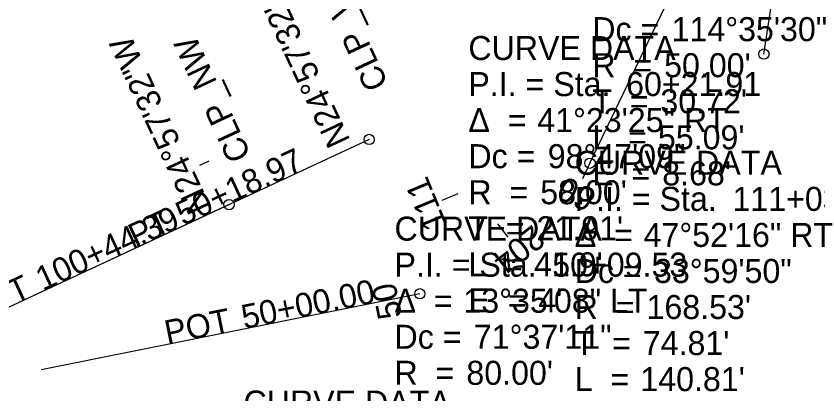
# Model space of a CAD drawing. Extents: x 1564517 to 1565226, y 635740 to 637455.
# Drawn here: x 1564729.9 to 1564823.3, y 636528.5 to 636572.5 of the extents above; entities that cross this region are included whole.
import ezdxf

# ---------------------------------------------------------------- set-up
doc = ezdxf.new("R2010")
doc.units = 0
for name, color, linetype in [('GK_Drainage_Nodes', 7, 'Continuous'), ('SC_Scratch10', 7, 'Continuous'), ('TX_P_1000', 7, 'Continuous'), ('UT_P_Water', 7, 'Continuous'), ('UT_P_Water_Cells', 7, 'Continuous'), ('UT_X_Sanitary_Pressure_Line', 7, 'Continuous'), ('UT_X_Water_Cells', 7, 'Continuous')]:
    doc.layers.add(name, color=color, linetype=linetype)

msp = doc.modelspace()

# ---------------------------------------------------------------- linework, layer by layer
at = {"layer": 'TX_P_1000'}
for p, q in [((1564796.769, 636555.382), (1564816.233, 636595.955)), ((1564771.061, 636558.156), (1564730.264, 636539.167)), ((1564776.961, 636540.174), (1564732.845, 636531.3))]:
    msp.add_line(p, q, dxfattribs=at)
at = {"layer": 'UT_P_Water_Cells'}
for p, q in [((1564817.022, 636568.096), (1564823.806, 636612.582)), ((1564796.769, 636555.382), (1564816.233, 636595.955)), ((1564771.061, 636558.156), (1564730.264, 636539.167)), ((1564796.769, 636555.382), (1564795.904, 636553.579)), ((1564781.384, 636551.813), (1564780.276, 636551.354)), ((1564754.742, 636550.56), (1564713.945, 636531.572)), ((1564785.988, 636548.34), (1564786.723, 636547.391)), ((1564776.961, 636540.174), (1564732.845, 636531.3)), ((1564776.961, 636540.174), (1564775.001, 636539.78))]:
    msp.add_line(p, q, dxfattribs=at)
for centre in [(1564817.022, 636568.096), (1564771.061, 636558.156), (1564796.769, 636555.382), (1564754.742, 636550.56), (1564776.961, 636540.174)]:
    msp.add_circle(centre, 0.6, dxfattribs=at)
at = {"layer": 'UT_X_Sanitary_Pressure_Line'}
for p, q in [((1564817.022, 636568.096), (1564823.806, 636612.582)), ((1564796.769, 636555.382), (1564816.233, 636595.955)), ((1564771.061, 636558.156), (1564730.264, 636539.167)), ((1564796.769, 636555.382), (1564795.904, 636553.579)), ((1564754.742, 636550.56), (1564713.945, 636531.572)), ((1564776.961, 636540.174), (1564732.845, 636531.3)), ((1564776.961, 636540.174), (1564775.001, 636539.78))]:
    msp.add_line(p, q, dxfattribs=at)
for centre in [(1564817.022, 636568.096), (1564771.061, 636558.156), (1564796.769, 636555.382), (1564754.742, 636550.56), (1564776.961, 636540.174)]:
    msp.add_circle(centre, 0.6, dxfattribs=at)
at = {"layer": 'UT_X_Water_Cells'}
for p, q in [((1564752.376, 636555.644), (1564751.288, 636555.137)), ((1564796.769, 636555.382), (1564795.904, 636553.579)), ((1564781.384, 636551.813), (1564779.536, 636551.049)), ((1564785.988, 636548.34), (1564787.213, 636546.759)), ((1564776.961, 636540.174), (1564775.001, 636539.78))]:
    msp.add_line(p, q, dxfattribs=at)
for centre in [(1564771.061, 636558.156), (1564796.769, 636555.382), (1564776.961, 636540.174)]:
    msp.add_circle(centre, 0.6, dxfattribs=at)

# ---------------------------------------------------------------- texts
at = {"layer": 'GK_Drainage_Nodes'}
for s, p in [('CLP_WL', (1564773.341, 636564.634)), ('N24°57\'32"W', (1564768.906, 636558.046)), ('N24°57\'32"W', (1564752.661, 636550.292)), ('CLP_NW', (1564757.357, 636556.318))]:
    msp.add_text(s, height=2.8, rotation=114.95884, dxfattribs=at).set_placement(p)
for s, p in [('Dc = ', (1564797.041, 636569.604)), ('114°35\'30"', (1564806.279, 636569.604)), ('CURVE DATA', (1564782.614, 636567.406)), ('R  = ', (1564797.041, 636565.404)), ("50.00'", (1564805.409, 636565.404)), ('P.I. = Sta. ', (1564782.614, 636563.206)), ('60+21.91', (1564800.983, 636563.206)), ('T  = ', (1564797.041, 636561.204)), ("30.72'", (1564804.973, 636561.204)), ('Δ  = ', (1564782.614, 636559.006)), ('41°23\'25" RT', (1564790.636, 636559.006)), ('L  = ', (1564797.041, 636557.004)), ("55.09'", (1564804.687, 636557.004)), ('Dc = ', (1564782.614, 636554.806)), ('98°47\'09"', (1564791.853, 636554.806)), ('CURVE DATA', (1564794.993, 636554.033)), ('E  = ', (1564797.041, 636552.804)), ("8.68'", (1564805.193, 636552.804)), ('R  = ', (1564782.614, 636550.606)), ("58.00'", (1564790.982, 636550.606)), ('P.I. = Sta. ', (1564794.993, 636549.833)), ('111+03.79', (1564813.362, 636549.833)), ('CURVE DATA', (1564774.011, 636546.365)), ('T  = ', (1564782.614, 636546.406)), ("21.91'", (1564790.547, 636546.406)), ('Δ  = ', (1564794.993, 636545.633)), ('47°52\'16" RT', (1564803.016, 636545.633)), ('P.I. = Sta. ', (1564774.011, 636542.165)), ('L  = ', (1564782.614, 636542.206)), ("41.9'", (1564790.261, 636542.206)), ('50+09.53', (1564792.38, 636542.165)), ('Dc = ', (1564794.993, 636541.433)), ('33°59\'50"', (1564804.232, 636541.433)), ('Δ  = ', (1564774.011, 636537.965)), ('13°35\'08" LT', (1564782.034, 636537.965)), ('E  = ', (1564782.614, 636538.006)), ("4'", (1564790.767, 636538.006)), ('R  = ', (1564794.993, 636537.233)), ("168.53'", (1564803.361, 636537.233)), ('Dc = ', (1564774.011, 636533.765)), ('71°37\'11"', (1564783.25, 636533.765)), ('T  = ', (1564794.993, 636533.033)), ("74.81'", (1564802.926, 636533.033)), ('R  = ', (1564774.011, 636529.565)), ("80.00'", (1564782.379, 636529.565)), ('L  = ', (1564794.993, 636528.833)), ("140.81'", (1564802.64, 636528.833)), ('CURVE DATA', (1564756.427, 636526.1))]:
    msp.add_text(s, height=2.8, dxfattribs=at).set_placement(p)
at = {"layer": 'SC_Scratch10'}
for s, p in [('CLP_WL', (1564773.341, 636564.634)), ('N24°57\'32"W', (1564768.906, 636558.046)), ('N24°57\'32"W', (1564752.661, 636550.292)), ('CLP_NW', (1564757.357, 636556.318))]:
    msp.add_text(s, height=2.8, rotation=114.95884, dxfattribs=at).set_placement(p)
for s, p in [('Dc = ', (1564797.041, 636569.604)), ('114°35\'30"', (1564806.279, 636569.604)), ('CURVE DATA', (1564782.614, 636567.406)), ('R  = ', (1564797.041, 636565.404)), ("50.00'", (1564805.409, 636565.404)), ('P.I. = Sta. ', (1564782.614, 636563.206)), ('60+21.91', (1564800.983, 636563.206)), ('T  = ', (1564797.041, 636561.204)), ("30.72'", (1564804.973, 636561.204)), ('Δ  = ', (1564782.614, 636559.006)), ('41°23\'25" RT', (1564790.636, 636559.006)), ('L  = ', (1564797.041, 636557.004)), ("55.09'", (1564804.687, 636557.004)), ('Dc = ', (1564782.614, 636554.806)), ('98°47\'09"', (1564791.853, 636554.806)), ('CURVE DATA', (1564794.993, 636554.033)), ('E  = ', (1564797.041, 636552.804)), ("8.68'", (1564805.193, 636552.804)), ('R  = ', (1564782.614, 636550.606)), ("58.00'", (1564790.982, 636550.606)), ('P.I. = Sta. ', (1564794.993, 636549.833)), ('111+03.79', (1564813.362, 636549.833)), ('CURVE DATA', (1564774.011, 636546.365)), ('T  = ', (1564782.614, 636546.406)), ("21.91'", (1564790.547, 636546.406)), ('Δ  = ', (1564794.993, 636545.633)), ('47°52\'16" RT', (1564803.016, 636545.633)), ('P.I. = Sta. ', (1564774.011, 636542.165)), ('L  = ', (1564782.614, 636542.206)), ("41.9'", (1564790.261, 636542.206)), ('50+09.53', (1564792.38, 636542.165)), ('Dc = ', (1564794.993, 636541.433)), ('33°59\'50"', (1564804.232, 636541.433)), ('Δ  = ', (1564774.011, 636537.965)), ('13°35\'08" LT', (1564782.034, 636537.965)), ('E  = ', (1564782.614, 636538.006)), ("4'", (1564790.767, 636538.006)), ('R  = ', (1564794.993, 636537.233)), ("168.53'", (1564803.361, 636537.233)), ('Dc = ', (1564774.011, 636533.765)), ('71°37\'11"', (1564783.25, 636533.765)), ('T  = ', (1564794.993, 636533.033)), ("74.81'", (1564802.926, 636533.033)), ('R  = ', (1564774.011, 636529.565)), ("80.00'", (1564782.379, 636529.565)), ('L  = ', (1564794.993, 636528.833)), ("140.81'", (1564802.64, 636528.833)), ('CURVE DATA', (1564756.427, 636526.1))]:
    msp.add_text(s, height=2.8, dxfattribs=at).set_placement(p)
at = {"layer": 'UT_P_Water'}
for s, p in [('CLP_WL', (1564773.341, 636564.634)), ('N24°57\'32"W', (1564768.906, 636558.046)), ('N24°57\'32"W', (1564752.661, 636550.292)), ('CLP_NW', (1564757.357, 636556.318))]:
    msp.add_text(s, height=2.8, rotation=114.95884, dxfattribs=at).set_placement(p)
for s, p in [('Dc = ', (1564797.041, 636569.604)), ('114°35\'30"', (1564806.279, 636569.604)), ('CURVE DATA', (1564782.614, 636567.406)), ('R  = ', (1564797.041, 636565.404)), ("50.00'", (1564805.409, 636565.404)), ('P.I. = Sta. ', (1564782.614, 636563.206)), ('60+21.91', (1564800.983, 636563.206)), ('T  = ', (1564797.041, 636561.204)), ("30.72'", (1564804.973, 636561.204)), ('Δ  = ', (1564782.614, 636559.006)), ('41°23\'25" RT', (1564790.636, 636559.006)), ('L  = ', (1564797.041, 636557.004)), ("55.09'", (1564804.687, 636557.004)), ('Dc = ', (1564782.614, 636554.806)), ('98°47\'09"', (1564791.853, 636554.806)), ('CURVE DATA', (1564794.993, 636554.033)), ('E  = ', (1564797.041, 636552.804)), ("8.68'", (1564805.193, 636552.804)), ('R  = ', (1564782.614, 636550.606)), ("58.00'", (1564790.982, 636550.606)), ('P.I. = Sta. ', (1564794.993, 636549.833)), ('111+03.79', (1564813.362, 636549.833)), ('CURVE DATA', (1564774.011, 636546.365)), ('T  = ', (1564782.614, 636546.406)), ("21.91'", (1564790.547, 636546.406)), ('Δ  = ', (1564794.993, 636545.633)), ('47°52\'16" RT', (1564803.016, 636545.633)), ('P.I. = Sta. ', (1564774.011, 636542.165)), ('L  = ', (1564782.614, 636542.206)), ("41.9'", (1564790.261, 636542.206)), ('50+09.53', (1564792.38, 636542.165)), ('Dc = ', (1564794.993, 636541.433)), ('33°59\'50"', (1564804.232, 636541.433)), ('Δ  = ', (1564774.011, 636537.965)), ('13°35\'08" LT', (1564782.034, 636537.965)), ('E  = ', (1564782.614, 636538.006)), ("4'", (1564790.767, 636538.006)), ('R  = ', (1564794.993, 636537.233)), ("168.53'", (1564803.361, 636537.233)), ('Dc = ', (1564774.011, 636533.765)), ('71°37\'11"', (1564783.25, 636533.765)), ('T  = ', (1564794.993, 636533.033)), ("74.81'", (1564802.926, 636533.033)), ('R  = ', (1564774.011, 636529.565)), ("80.00'", (1564782.379, 636529.565)), ('L  = ', (1564794.993, 636528.833)), ("140.81'", (1564802.64, 636528.833)), ('CURVE DATA', (1564756.427, 636526.1))]:
    msp.add_text(s, height=2.8, dxfattribs=at).set_placement(p)
at = {"layer": 'UT_P_Water_Cells'}
for s, rotation, p in [('50+18.97', 24.95884, (1564749.381, 636548.065)), ('60', 154.37239, (1564797.645, 636552.137)), ('100+44.39', 24.95884, (1564733.062, 636540.47)), ('PT', 24.95884, (1564743.863, 636545.497)), ('PT', 24.95884, (1564727.544, 636537.901)), ('50+00.00', 11.37328, (1564756.501, 636536.059)), ('50', 101.37328, (1564774.897, 636537.522)), ('POT', 11.37328, (1564747.551, 636534.258))]:
    msp.add_text(s, height=2.8, rotation=rotation, dxfattribs=at).set_placement(p)
at = {"layer": 'UT_X_Sanitary_Pressure_Line'}
for s, rotation, p in [('50+18.97', 24.95884, (1564749.381, 636548.065)), ('60', 154.37239, (1564797.645, 636552.137)), ('100+44.39', 24.95884, (1564733.062, 636540.47)), ('PT', 24.95884, (1564743.863, 636545.497)), ('PT', 24.95884, (1564727.544, 636537.901)), ('50+00.00', 11.37328, (1564756.501, 636536.059)), ('50', 101.37328, (1564774.897, 636537.522)), ('POT', 11.37328, (1564747.551, 636534.258))]:
    msp.add_text(s, height=2.8, rotation=rotation, dxfattribs=at).set_placement(p)
at = {"layer": 'UT_X_Water_Cells'}
for s, rotation, p in [('111', 112.47396, (1564780.153, 636548.25)), ('60', 154.37239, (1564797.645, 636552.137)), ('204', 217.76888, (1564790.108, 636548.31)), ('50', 101.37328, (1564774.897, 636537.522))]:
    msp.add_text(s, height=2.8, rotation=rotation, dxfattribs=at).set_placement(p)

doc.saveas('drawing.dxf')
